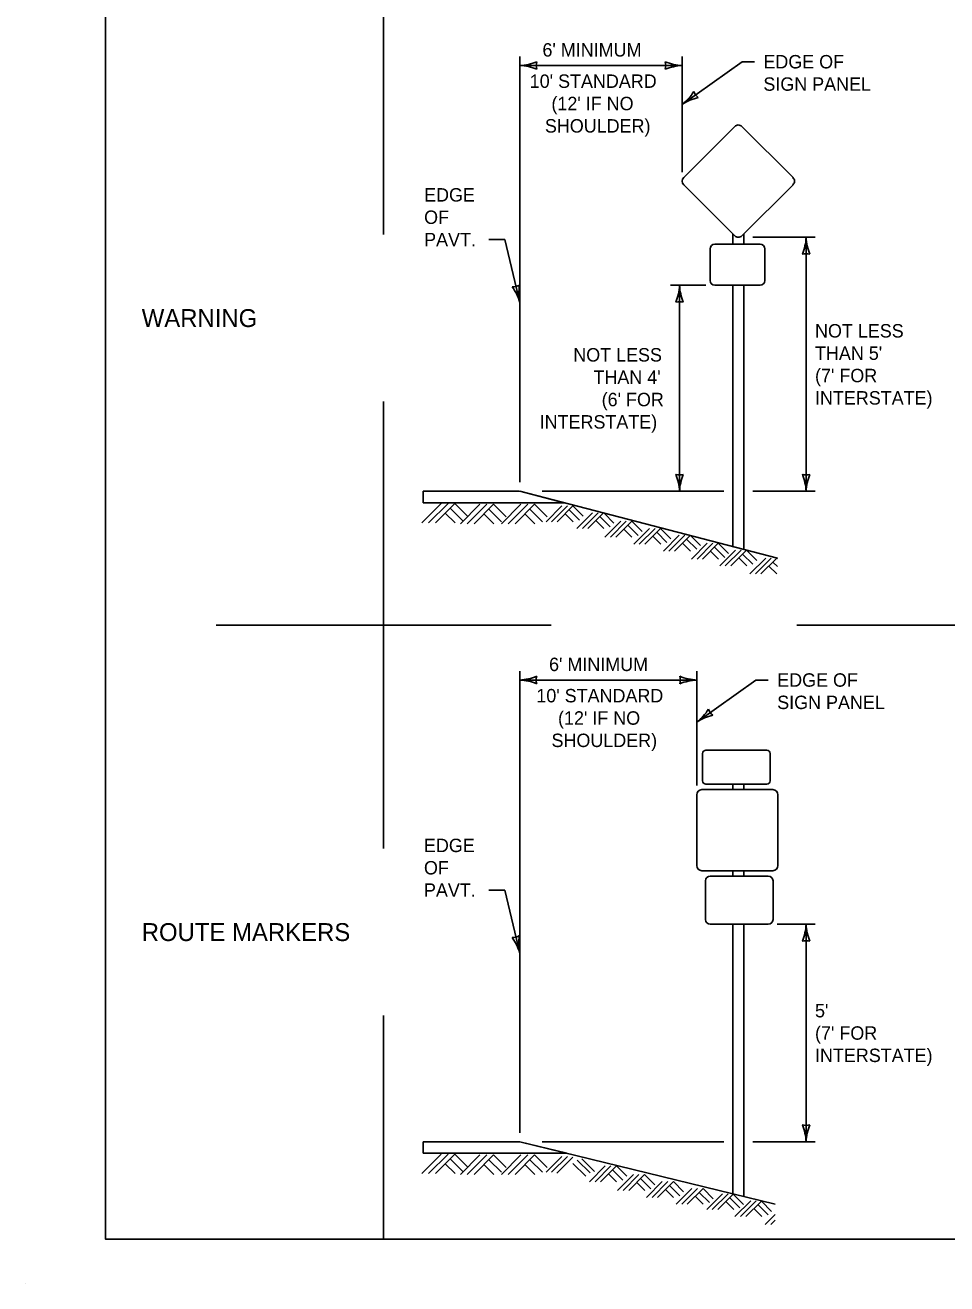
# Model space of a CAD drawing. Extents: x 49991.4 to 50021, y 49987.6 to 50011.4.
# Drawn here: x 49999.02 to 50003.15, y 49987.6 to 49993.23 of the extents above; entities that cross this region are included whole.
import ezdxf

# ---------------------------------------------------------------- set-up
doc = ezdxf.new("R2010")
doc.units = 0
for name, color, linetype in [('Level 1', 7, 'Continuous'), ('Level 2', 7, 'Continuous'), ('Level 3', 7, 'Continuous')]:
    doc.layers.add(name, color=color, linetype=linetype)

msp = doc.modelspace()

# ---------------------------------------------------------------- linework, layer by layer
at = {"layer": 'Level 1'}
for p, q in [((50001.9717, 49992.5484), (50002.2003, 49992.7772)), ((50002.2321, 49992.7772), (50002.461, 49992.5484)), ((50002.2003, 49992.2877), (50001.9717, 49992.5166)), ((50002.461, 49992.5166), (50002.2321, 49992.2877)), ((50002.1919, 49992.2506), (50002.1919, 49992.2961)), ((50002.2405, 49992.2506), (50002.2405, 49992.2961)), ((50002.0896, 49992.0878), (50002.0896, 49992.2291)), ((50002.1111, 49992.2506), (50002.3137, 49992.2506)), ((50002.3352, 49992.2291), (50002.3352, 49992.0878)), ((50002.3137, 49992.0663), (50002.1111, 49992.0663)), ((50002.1919, 49990.8971), (50002.1919, 49992.0663)), ((50002.2406, 49990.8844), (50002.2406, 49992.0663)), ((50001.2376, 49991.1452), (50000.8056, 49991.1452)), ((50000.8056, 49991.1452), (50000.8056, 49991.0936)), ((50001.2376, 49991.1452), (50000.8056, 49991.1452)), ((50000.8056, 49991.1452), (50000.8056, 49991.0936)), ((50001.2379, 49991.1452), (50002.3914, 49990.8452)), ((50001.4363, 49991.0936), (50001.2379, 49991.1452)), ((50000.7994, 49991.003), (50000.8867, 49991.0903)), ((50000.8056, 49991.0936), (50001.4364, 49991.0936)), ((50000.8056, 49991.0936), (50001.4363, 49991.0936)), ((50000.8301, 49991.003), (50000.9174, 49991.0903)), ((50000.8605, 49991.003), (50000.9478, 49991.0903)), ((50000.9478, 49991.0903), (50001.0047, 49991.0335)), ((50000.9722, 49990.9993), (50001.0595, 49991.0867)), ((50001.0029, 49990.9993), (50001.0902, 49991.0867)), ((50001.0334, 49990.9993), (50001.1207, 49991.0867)), ((50001.1207, 49991.0867), (50001.1776, 49991.0299)), ((50001.1557, 49990.9993), (50001.243, 49991.0867)), ((50001.1864, 49990.9993), (50001.2737, 49991.0867)), ((50001.2168, 49990.9993), (50001.3042, 49991.0867)), ((50001.3042, 49991.0867), (50001.3611, 49991.0299)), ((50001.4361, 49991.0936), (50001.4361, 49991.0936)), ((50000.9047, 49991.047), (50000.9488, 49991.003)), ((50000.9264, 49991.0687), (50000.9831, 49991.0121)), ((50001.0775, 49991.0434), (50001.1216, 49990.9993)), ((50001.0991, 49991.0651), (50001.1558, 49991.0084)), ((50001.261, 49991.0434), (50001.3051, 49990.9993)), ((50001.2826, 49991.0651), (50001.3393, 49991.0084)), ((50001.356, 49991.0088), (50001.4267, 49991.0795)), ((50001.3808, 49991.0088), (50001.4515, 49991.0795)), ((50001.4054, 49991.0088), (50001.4761, 49991.0795)), ((50001.4412, 49991.0446), (50001.4771, 49991.0088)), ((50001.4587, 49991.0622), (50001.5048, 49991.0162)), ((50001.4761, 49991.0795), (50001.5222, 49991.0335)), ((50001.4934, 49990.9781), (50001.5641, 49991.0488)), ((50001.5182, 49990.9781), (50001.5889, 49991.0488)), ((50001.5428, 49990.9781), (50001.6126, 49991.0477)), ((50001.5962, 49991.0315), (50001.6422, 49990.9855)), ((50001.6155, 49991.047), (50001.6596, 49991.0028)), ((50001.5786, 49991.0138), (50001.6145, 49990.9781)), ((50001.6191, 49990.9398), (50001.6898, 49991.0105)), ((50001.644, 49990.9398), (50001.7147, 49991.0105)), ((50001.6686, 49990.9398), (50001.7393, 49991.0105)), ((50001.7044, 49990.9756), (50001.7402, 49990.9398)), ((50001.722, 49990.9931), (50001.7679, 49990.9472)), ((50001.7393, 49991.0105), (50001.7854, 49990.9645)), ((50001.7482, 49990.908), (50001.8189, 49990.9788)), ((50001.7732, 49990.908), (50001.8439, 49990.9788)), ((50001.7978, 49990.908), (50001.8685, 49990.9788)), ((50001.8685, 49990.9788), (50001.9146, 49990.9327)), ((50001.8336, 49990.9437), (50001.8693, 49990.908)), ((50001.851, 49990.9614), (50001.897, 49990.9154)), ((50001.881, 49990.8776), (50001.9517, 49990.9483)), ((50001.9058, 49990.8776), (50001.9767, 49990.9483)), ((50001.9306, 49990.8776), (50002, 49990.947)), ((50001.9664, 49990.9132), (50002.002, 49990.8776)), ((50001.9838, 49990.9308), (50002.0298, 49990.8851)), ((50002.0035, 49990.9461), (50002.0474, 49990.9024)), ((50002.0065, 49990.8418), (50002.0772, 49990.9126)), ((50002.0315, 49990.8418), (50002.1022, 49990.9126)), ((50002.056, 49990.8418), (50002.1267, 49990.9126)), ((50002.0918, 49990.8776), (50002.1275, 49990.8418)), ((50002.1092, 49990.8951), (50002.1553, 49990.8492)), ((50002.1267, 49990.9126), (50002.1729, 49990.8665)), ((50002.1328, 49990.8107), (50002.2035, 49990.8814)), ((50002.1576, 49990.8107), (50002.2284, 49990.8814)), ((50002.1822, 49990.8107), (50002.2529, 49990.8812)), ((50002.2356, 49990.864), (50002.2816, 49990.8181)), ((50002.2534, 49990.8811), (50002.2992, 49990.8355)), ((50002.2181, 49990.8464), (50002.2538, 49990.8107)), ((50002.2681, 49990.7748), (50002.3388, 49990.8455)), ((50002.2931, 49990.7748), (50002.3638, 49990.8455)), ((50002.3176, 49990.7748), (50002.3884, 49990.8455)), ((50002.3535, 49990.8105), (50002.3893, 49990.7748)), ((50002.3709, 49990.8281), (50002.3914, 49990.8076)), ((50002.3884, 49990.8455), (50002.3914, 49990.8425)), ((50002.0565, 49989.8499), (50002.0565, 49989.9711)), ((50002.0715, 49989.9861), (50002.3436, 49989.9861)), ((50002.3586, 49989.9711), (50002.3586, 49989.8499)), ((50002.0306, 49989.4698), (50002.0306, 49989.7873)), ((50002.0531, 49989.8098), (50002.3707, 49989.8098)), ((50002.3436, 49989.8349), (50002.0715, 49989.8349)), ((50002.192, 49989.8098), (50002.192, 49989.8349)), ((50002.2406, 49989.8098), (50002.2406, 49989.8349)), ((50002.3932, 49989.7873), (50002.3932, 49989.4698)), ((50002.3707, 49989.4473), (50002.0531, 49989.4473)), ((50002.0693, 49989.229), (50002.0693, 49989.4019)), ((50002.0908, 49989.4234), (50002.35, 49989.4234)), ((50002.192, 49989.4234), (50002.192, 49989.4473)), ((50002.2406, 49989.4234), (50002.2406, 49989.4473)), ((50002.3715, 49989.4019), (50002.3715, 49989.229)), ((50002.35, 49989.2075), (50002.0908, 49989.2075)), ((50002.192, 49988.0012), (50002.192, 49989.2075)), ((50002.2406, 49987.9893), (50002.2406, 49989.2075)), ((50001.2376, 49988.2345), (50000.8056, 49988.2345)), ((50000.8056, 49988.2345), (50000.8056, 49988.1828)), ((50001.2376, 49988.2345), (50000.8056, 49988.2345)), ((50000.8056, 49988.2345), (50000.8056, 49988.1828)), ((50001.2377, 49988.2345), (50002.3813, 49987.9549)), ((50001.4491, 49988.1828), (50001.2377, 49988.2345)), ((50000.7994, 49988.0922), (50000.8867, 49988.1796)), ((50000.8056, 49988.1828), (50001.4491, 49988.1828)), ((50000.8056, 49988.1828), (50001.4491, 49988.1828)), ((50000.8301, 49988.0922), (50000.9174, 49988.1796)), ((50000.8605, 49988.0922), (50000.9479, 49988.1796)), ((50000.9264, 49988.158), (50000.9832, 49988.1013)), ((50000.9479, 49988.1796), (50001.0047, 49988.1228)), ((50000.9722, 49988.0886), (50001.0596, 49988.1759)), ((50001.0029, 49988.0886), (50001.0902, 49988.1759)), ((50001.0334, 49988.0886), (50001.1207, 49988.1759)), ((50001.0991, 49988.1543), (50001.1559, 49988.0977)), ((50001.1207, 49988.1759), (50001.1776, 49988.1192)), ((50001.1557, 49988.0886), (50001.2431, 49988.1759)), ((50001.1864, 49988.0886), (50001.2737, 49988.1759)), ((50001.2169, 49988.0886), (50001.3042, 49988.1759)), ((50001.2826, 49988.1543), (50001.3394, 49988.0977)), ((50001.3042, 49988.1759), (50001.3611, 49988.1192)), ((50001.356, 49988.0981), (50001.4267, 49988.1688)), ((50001.3808, 49988.0981), (50001.4515, 49988.1688)), ((50001.4044, 49988.0941), (50001.4751, 49988.1648)), ((50001.5157, 49988.1583), (50001.5726, 49988.1016)), ((50000.9047, 49988.1363), (50000.9488, 49988.0922)), ((50001.0775, 49988.1326), (50001.1217, 49988.0886)), ((50001.261, 49988.1326), (50001.3051, 49988.0886)), ((50001.4762, 49988.1379), (50001.5331, 49988.0812)), ((50001.4957, 49988.1519), (50001.5526, 49988.0952)), ((50001.5503, 49988.0553), (50001.621, 49988.126)), ((50001.5751, 49988.0553), (50001.6458, 49988.126)), ((50001.5998, 49988.0553), (50001.6706, 49988.126)), ((50001.6531, 49988.1086), (50001.6991, 49988.0627)), ((50001.6706, 49988.126), (50001.7166, 49988.08)), ((50001.6355, 49988.0909), (50001.6714, 49988.0553)), ((50001.676, 49988.017), (50001.7467, 49988.0877)), ((50001.7009, 49988.017), (50001.7716, 49988.0877)), ((50001.7255, 49988.017), (50001.7962, 49988.0877)), ((50001.7613, 49988.0527), (50001.7971, 49988.017)), ((50001.7789, 49988.0703), (50001.8249, 49988.0244)), ((50001.7962, 49988.0877), (50001.8423, 49988.0417)), ((50001.8051, 49987.9852), (50001.8758, 49988.056)), ((50001.8301, 49987.9852), (50001.9008, 49988.056)), ((50001.8547, 49987.9852), (50001.9254, 49988.056)), ((50001.9254, 49988.056), (50001.9715, 49988.0099)), ((50001.8905, 49988.0208), (50001.9262, 49987.9852)), ((50001.9079, 49988.0385), (50001.9539, 49987.9926)), ((50001.9379, 49987.9547), (50002.0086, 49988.0254)), ((50001.9627, 49987.9547), (50002.0336, 49988.0254)), ((50001.9875, 49987.9547), (50002.0582, 49988.0254)), ((50002.0233, 49987.9904), (50002.0589, 49987.9547)), ((50002.0407, 49988.008), (50002.0867, 49987.9623)), ((50002.0582, 49988.0254), (50002.1043, 49987.9796)), ((50002.0746, 49987.9311), (50002.1453, 49988.0019)), ((50002.0996, 49987.9311), (50002.1703, 49988.0019)), ((50002.1241, 49987.9311), (50002.1927, 49987.9998)), ((50002.1773, 49987.9844), (50002.2234, 49987.9385)), ((50002.1927, 49987.9998), (50002.2389, 49987.9537)), ((50002.1599, 49987.9668), (50002.1956, 49987.9311)), ((50002.2009, 49987.9), (50002.2716, 49987.9707)), ((50002.2257, 49987.9), (50002.2966, 49987.9707)), ((50002.2503, 49987.9), (50002.3194, 49987.9689)), ((50002.2862, 49987.9357), (50002.3219, 49987.9)), ((50002.3037, 49987.9533), (50002.3497, 49987.9074)), ((50002.3193, 49987.969), (50002.3654, 49987.9231)), ((50002.3362, 49987.8641), (50002.3813, 49987.9092)), ((50002.3612, 49987.8641), (50002.3813, 49987.8842)), ((49999.0245, 49987.5988), (49999.0245, 49987.5988))]:
    msp.add_line(p, q, dxfattribs=at)
msp.add_lwpolyline([(49999.3835, 49998.9992), (50016.7501, 49998.9992), (50016.7501, 49987.7988), (49999.3835, 49987.7988)], close=True, dxfattribs=at)
for centre, radius, start, end in [((50002.2162, 49992.7613), 0.0225, 45.011, 135.022), ((50001.9876, 49992.5325), 0.0225, 135.022, 224.967), ((50002.445, 49992.5325), 0.0225, 315, 45.011), ((50002.2162, 49992.3036), 0.0225, 224.967, 315), ((50002.1111, 49992.2291), 0.0215, 90, 180), ((50002.3137, 49992.2291), 0.0215, 0, 90), ((50002.1111, 49992.0878), 0.0215, 180, 270), ((50002.3137, 49992.0878), 0.0215, 270, 0), ((50002.0715, 49989.9711), 0.015, 90, 180), ((50002.3436, 49989.9711), 0.015, 0, 90), ((50002.0715, 49989.8499), 0.015, 180, 270), ((50002.3436, 49989.8499), 0.015, 270, 0), ((50002.0531, 49989.7873), 0.0225, 90, 180), ((50002.3707, 49989.7873), 0.0225, 0, 90), ((50002.0531, 49989.4698), 0.0225, 180, 270), ((50002.3707, 49989.4698), 0.0225, 270, 0), ((50002.0908, 49989.4019), 0.0215, 90, 180), ((50002.35, 49989.4019), 0.0215, 0, 90), ((50002.0908, 49989.229), 0.0215, 180, 270), ((50002.35, 49989.229), 0.0215, 270, 0)]:
    msp.add_arc(centre, radius, start, end, dxfattribs=at)
at = {"layer": 'Level 3'}
for p, q in [((50000.6286, 49992.2934), (50000.6286, 49994.2934)), ((50001.2384, 49991.1852), (50001.2384, 49993.0898)), ((50001.9651, 49992.5725), (50001.9651, 49993.0898)), ((50001.9651, 49992.876), (50002.233, 49993.0668)), ((50002.233, 49993.0668), (50002.2884, 49993.0668)), ((50001.9651, 49993.0498), (50001.2384, 49993.0498)), ((50001.0996, 49992.2711), (50001.1716, 49992.2711)), ((50001.1716, 49992.2711), (50001.2384, 49991.9896)), ((50002.2805, 49992.2811), (50002.5595, 49992.2811)), ((50002.5195, 49992.2811), (50002.5195, 49991.1446)), ((50001.9133, 49992.0663), (50002.0711, 49992.0663)), ((50001.9533, 49992.0663), (50001.9533, 49991.1446)), ((50000.6286, 49989.5461), (50000.6286, 49991.5461)), ((50001.3379, 49991.1446), (50002.1519, 49991.1446)), ((50002.2806, 49991.1446), (50002.5595, 49991.1446)), ((49999.8786, 49990.5461), (50001.3786, 49990.5461)), ((50002.4787, 49990.5461), (50003.9787, 49990.5461)), ((50001.2377, 49988.2745), (50001.2377, 49990.3404)), ((50002.0306, 49990.3004), (50001.2377, 49990.3004)), ((50002.0306, 49989.8286), (50002.0306, 49990.3404)), ((50002.0306, 49990.1122), (50002.2949, 49990.3004)), ((50002.2949, 49990.3004), (50002.3503, 49990.3004)), ((50001.0989, 49989.3604), (50001.1709, 49989.3604)), ((50001.1709, 49989.3604), (50001.2377, 49989.0789)), ((50002.39, 49989.2075), (50002.5595, 49989.2075)), ((50002.5195, 49989.2075), (50002.5195, 49988.2345)), ((50000.6286, 49988.7988), (50000.6286, 49987.7988)), ((50001.3377, 49988.2345), (50002.152, 49988.2345)), ((50002.2806, 49988.2345), (50002.5595, 49988.2345))]:
    msp.add_line(p, q, dxfattribs=at)
for centre, radius, start, end in [((50001.2269, 49993.2825), 0.233, 272.8273, 292.0772), ((50001.3666, 49993.0498), 0.0548, 162.1388, 197.8612), ((50001.9743, 49993.2719), 0.2223, 247.456, 267.6395), ((50001.8369, 49993.0498), 0.0548, 342.1388, 17.8612), ((50001.2292, 49992.8277), 0.2223, 67.456, 87.6395), ((50001.9766, 49992.8171), 0.233, 92.8273, 112.0772), ((50001.8207, 49993.0589), 0.233, 308.286, 327.5359), ((50002.0865, 49992.6898), 0.2223, 102.9147, 123.0982), ((50002.0695, 49992.9504), 0.0548, 197.5975, 233.3199), ((50002.2974, 49992.2903), 0.2223, 337.456, 357.6395), ((50002.7522, 49992.2926), 0.233, 182.8273, 202.0772), ((50002.5195, 49992.1529), 0.0548, 72.1388, 107.8612), ((50001.2088, 49992.1144), 0.0548, 265.4882, 301.2106), ((50001.0146, 49991.9247), 0.233, 16.1767, 35.4265), ((50001.4566, 49992.032), 0.2223, 170.8054, 190.9889), ((50001.7312, 49992.0755), 0.2223, 337.456, 357.6395), ((50002.186, 49992.0778), 0.233, 182.8273, 202.0772), ((50001.9533, 49991.9381), 0.0548, 72.1388, 107.8612), ((50001.9533, 49991.2728), 0.0548, 252.1388, 287.8612), ((50001.7206, 49991.1331), 0.233, 2.8273, 22.0772), ((50002.1754, 49991.1354), 0.2223, 157.456, 177.6395), ((50002.5195, 49991.2728), 0.0548, 252.1388, 287.8612), ((50002.2868, 49991.1331), 0.233, 2.8273, 22.0772), ((50002.7416, 49991.1354), 0.2223, 157.456, 177.6395), ((50001.2262, 49990.5331), 0.233, 272.8273, 292.0772), ((50001.2285, 49990.0783), 0.2223, 67.456, 87.6395), ((50001.3659, 49990.3004), 0.0548, 162.1388, 197.8612), ((50002.0398, 49990.5225), 0.2223, 247.456, 267.6395), ((50001.9024, 49990.3004), 0.0548, 342.1388, 17.8612), ((50002.0421, 49990.0677), 0.233, 92.8273, 112.0772), ((50001.8863, 49990.2951), 0.233, 308.2808, 327.5307), ((50002.152, 49989.9259), 0.2223, 102.9095, 123.093), ((50002.135, 49990.1866), 0.0548, 197.5923, 233.3147), ((50002.2974, 49989.2167), 0.2223, 337.456, 357.6395), ((50002.7522, 49989.219), 0.233, 182.8273, 202.0772), ((50001.2081, 49989.2037), 0.0548, 265.4882, 301.2106), ((50001.0139, 49989.014), 0.233, 16.1767, 35.4265), ((50001.4559, 49989.1213), 0.2223, 170.8054, 190.9889), ((50002.5195, 49989.0793), 0.0548, 72.1388, 107.8612), ((50002.5195, 49988.3627), 0.0548, 252.1388, 287.8612), ((50002.2868, 49988.223), 0.233, 2.8273, 22.0772), ((50002.7416, 49988.2253), 0.2223, 157.456, 177.6395)]:
    msp.add_arc(centre, radius, start, end, dxfattribs=at)

# ---------------------------------------------------------------- texts
at = {"layer": 'Level 2'}
for s, height, p in [("6' MINIMUM", 0.06, (50001.3396, 49993.0898)), ('EDGE OF', 0.06, (50002.3284, 49993.0368)), ("10' STANDARD", 0.06, (50001.2827, 49992.9498)), ('SIGN PANEL', 0.06, (50002.3284, 49992.9368)), ("(12' IF NO", 0.06, (50001.3798, 49992.8498)), ('SHOULDER)', 0.06, (50001.3506, 49992.7498)), ('EDGE', 0.06, (50000.81, 49992.4411)), ('OF', 0.06, (50000.81, 49992.3411)), ('PAVT.', 0.06, (50000.81, 49992.2411)), ('WARNING', 0.08, (49999.5462, 49991.8798)), ('NOT LESS', 0.06, (50002.5595, 49991.8328)), ('NOT LESS', 0.06, (50001.4776, 49991.7254)), ("THAN 5'", 0.06, (50002.5595, 49991.7328)), ("THAN 4'", 0.06, (50001.568, 49991.6254)), ("(7' FOR", 0.06, (50002.5595, 49991.6328)), ("(6' FOR", 0.06, (50001.6046, 49991.5254)), ('INTERSTATE)', 0.06, (50002.5595, 49991.5328)), ('INTERSTATE)', 0.06, (50001.3272, 49991.4254)), ("6' MINIMUM", 0.06, (50001.3692, 49990.3404)), ('EDGE OF', 0.06, (50002.3903, 49990.2704)), ("10' STANDARD", 0.06, (50001.3123, 49990.2004)), ('SIGN PANEL', 0.06, (50002.3903, 49990.1704)), ("(12' IF NO", 0.06, (50001.4094, 49990.1004)), ('SHOULDER)', 0.06, (50001.3802, 49990.0004)), ('EDGE', 0.06, (50000.8093, 49989.5304)), ('OF', 0.06, (50000.8093, 49989.4304)), ('PAVT.', 0.06, (50000.8093, 49989.3304)), ('ROUTE MARKERS', 0.08, (49999.5462, 49989.1325)), ("5'", 0.06, (50002.5595, 49988.791)), ("(7' FOR", 0.06, (50002.5595, 49988.691)), ('INTERSTATE)', 0.06, (50002.5595, 49988.591))]:
    msp.add_text(s, height=height, dxfattribs=at).set_placement(p)

doc.saveas('drawing.dxf')
